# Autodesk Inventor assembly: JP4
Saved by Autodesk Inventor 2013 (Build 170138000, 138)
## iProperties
Created: 2021-02
Part Number: JP4
Document SubType Name: Assembly
Designer: Fede
Author: Fede
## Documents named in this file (2)
- C:\0000 FEDE\16GB\0000 INTERIOR\DE_TMP_BAS\BAS_DTON - demora conexion al energizar\DTON_MANUAL\img\INVENTOR\BAS_DTON - SIN R\JP4.iam
- C:\0000 FEDE\16GB\0000 INTERIOR\DE_TMP_BAS\BAS_DTON - demora conexion al energizar\DTON_MANUAL\img\INVENTOR\BAS_DTON - SIN R\bornera3x1.iam
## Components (1 placed, 1 different names)
1. bornera3x1:1 [sub-assembly]
